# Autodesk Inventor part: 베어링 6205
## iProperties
Created: 2009-02
Part Number: 베어링 6205
Material: 강, 연강
Description: 깊은 그루브 볼 베어링
Document SubType Name: Modeling
Standard: KS B 2023
Designer: SeoGD™[esajin.kr]
Standards Organization: KS
Language: ko-KR
Size Designation: 6205 - 25 x 52 x 15
Categories: <MemberInstance><Categories><Category DisplayName="샤프트 부품" InternalName="7f7aeb1f-a693-4053-b835-cee3144e0d98" Mnemonic="SHFT"><Category DisplayName="베어링" Inter
Density: 1 g/cm^3
IsCustomPart: 1
Author: SeoGD™[esajin.kr]
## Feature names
1. IDS_ARRAYBALL[SIMPL:T] [Circular Pattern]
